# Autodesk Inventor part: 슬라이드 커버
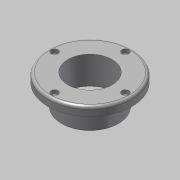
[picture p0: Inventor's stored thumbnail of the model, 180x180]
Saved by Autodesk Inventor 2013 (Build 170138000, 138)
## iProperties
Created: 2015-10
Part Number: 슬라이드 커버
Document SubType Name: Modeling
Designer: mdu
Density: 7.86 g/cm^3
Material: 강철, 연강
Mass: 633.012 g
Surface Area: 239.629 cm^2
Volume: 80.5358 cm^3
Author: mdu
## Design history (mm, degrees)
sketch "스케치1"
  geometry: C1 r 47.5 at (0, 0); C2 r 32.5 at (0, 0); 1 further point
  constraints: 2 centre point, 2 coincident
  dimensions: "d33" = 95 diameter of C1; "d35" = 65 diameter of C2
extrude "돌출1" new body sketch "스케치1" distance "d0" = 10; taper "d1" = 0 deg
extrude "돌출2" join sketch "스케치1" distance "d2" = 25; taper "d3" = 0 deg
hole "구멍1" diameter "d6" = 50; stored, may be unused: countersink angle "d10" = 90 deg, drill point angle "d12" = 118 deg; dims "d4" = 10, "d5" = 10, "d7" = 6, "d8" = 4, "d9" = 2, "d11" = 8
sketch "스케치2" dims "d36" = 80
  geometry: 4 further points
  constraints: 2 coincident, 2 vertical alignment, 2 other
hole "구멍2" sketch "스케치2" at (0, 40) diameter "d13" = 4.5; stored, may be unused: countersink angle "d17" = 90 deg, drill point angle "d19" = 118 deg; dims "d14" = 6, "d15" = 8, "d16" = 4.4, "d18" = 8
fillet "모깎기1" dims "d23" = 3
chamfer "모따기1" distance "d24" = 1; stored, may be unused: second distance "d25" = 2, angle "d26" = 45 deg
sketch "스케치3"
  geometry: C1 r 25 at (0, 0); C2 r 30 at (0, 0); C3 r 26 at (0, 0) reference; 1 further point
  constraints: 2 centre point, 2 coincident
  dimensions: "d27" = 60 diameter of C2
extrude "돌출3" cut sketch "스케치3" distance "d28" = 3; taper "d29" = 0 deg
chamfer "모따기2" distance "d30" = 1; stored, may be unused: second distance "d31" = 2, angle "d32" = 45 deg
node "솔리드1"
pattern_circular "원형 패턴1" dims angle "d21" = 360 deg
